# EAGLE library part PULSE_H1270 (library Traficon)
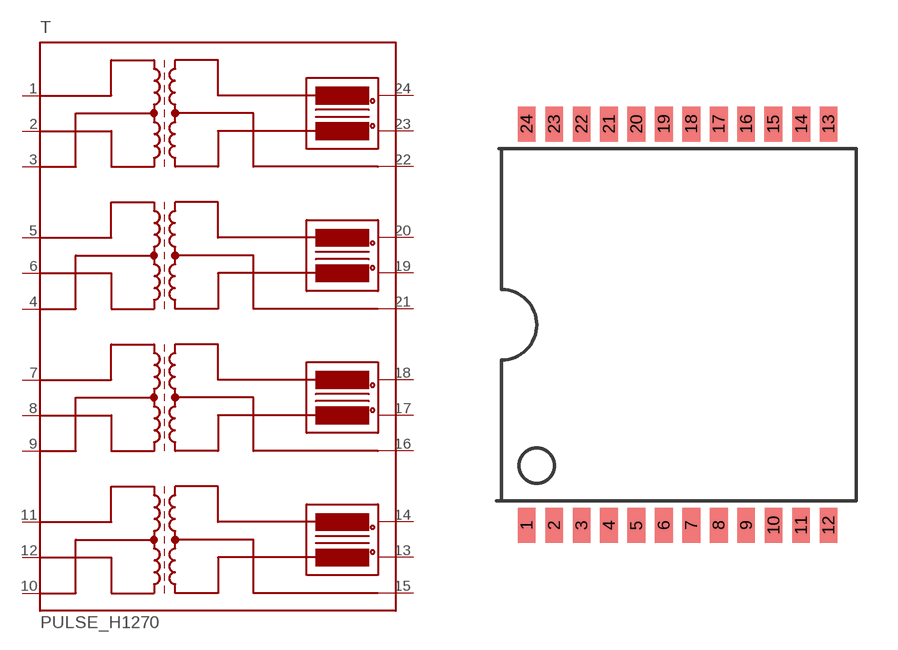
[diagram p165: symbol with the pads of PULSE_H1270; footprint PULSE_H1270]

Designator prefix T

## PULSE_H1270  [PULSE_H1270]
1  +TD1  pas
2  -TD1  pas
3  TDCT1  pas
4  RDCT2  pas
5  +RD2  pas
6  -RD2  pas
7  +TD3  pas
8  -TD3  pas
9  TDCT3  pas
10  RDCT4  pas
11  +RD4  pas
12  -RD4  pas
13  -RX4  pas
14  +RX4  pas
15  RXCT4  pas
16  TXCT3  pas
17  -TX3  pas
18  +TX3  pas
19  -RX2  pas
20  +RX2  pas
21  RXCT2  pas
22  TXCT1  pas
23  -TX1  pas
24  +TX1  pas

## Footprint PULSE_H1270 (pad centres in mm)
CT (12/03/2008): changed pin names to make it easier to check the package added half circle in silkscreen
smd 0.64 x 1.27: 1 -5.445,-7.24; 2 -4.455,-7.24; 3 -3.465,-7.24; 4 -2.475,-7.24; 5 -1.485,-7.24; 6 -0.495,-7.24; 7 0.495,-7.24; 8 1.485,-7.24; 9 2.475,-7.24; 10 3.465,-7.24; 11 4.455,-7.24; 12 5.445,-7.24; 13 5.445,7.24; 14 4.465,7.24; 15 3.455,7.24; 16 2.475,7.24; 17 1.485,7.24; 18 0.495,7.24; 19 -0.495,7.24; 20 -1.485,7.24; 21 -2.475,7.24; 22 -3.465,7.24; 23 -4.455,7.24; 24 -5.445,7.24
